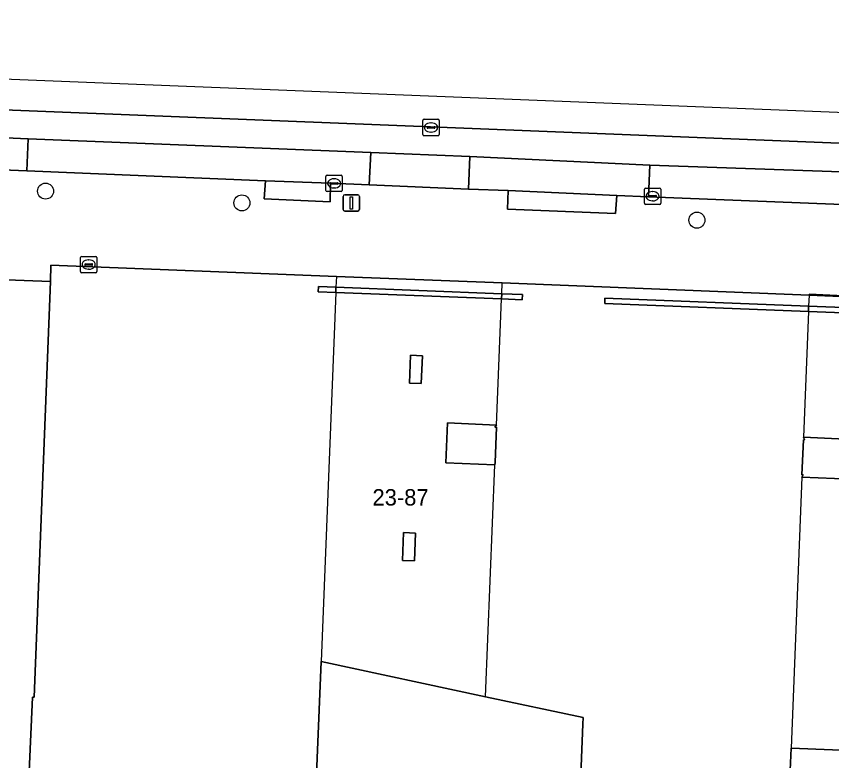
# Model space of a CAD drawing. Extents: x 160888 to 161385, y 386490 to 386908.
# Drawn here: x 161220.29 to 161269.97, y 386857.07 to 386902.41 of the extents above; entities that cross this region are included whole.
import ezdxf

# ---------------------------------------------------------------- set-up
doc = ezdxf.new("R2010")
doc.units = 0
for name, color, linetype in [('IMGEO_Boom', 7, 'Continuous'), ('IMGEO_Erf', 7, 'Continuous'), ('IMGEO_Hek', 7, 'Continuous'), ('IMGEO_Kolk', 7, 'Continuous'), ('IMGEO_Lichtmast', 7, 'Continuous'), ('IMGEO_Muur', 7, 'Continuous'), ('IMGEO_Pand', 7, 'Continuous'), ('IMGEO_Pand_nummerreeks', 7, 'Continuous'), ('IMGEO_Pand_overbouw', 7, 'Continuous'), ('IMGEO_Parkeervlak_gesloten', 7, 'Continuous'), ('IMGEO_Rijbaan_lokaal_gesloten', 7, 'Continuous'), ('IMGEO_Rioolput', 7, 'Continuous'), ('IMGEO_Voetpad_open', 7, 'Continuous')]:
    doc.layers.add(name, color=color, linetype=linetype)

msp = doc.modelspace()

# ---------------------------------------------------------------- linework, layer by layer
at = {"layer": 'IMGEO_Boom'}
for centre in [(161222.068, 386891.761), (161234.033, 386891.042), (161261.759, 386889.993)]:
    msp.add_circle(centre, 0.489, dxfattribs=at)
at = {"layer": 'IMGEO_Erf'}
msp.add_lwpolyline([(161278.689, 386885.003), (161268.594, 386885.414), (161249.896, 386886.171), (161239.793, 386886.567), (161222.396, 386887.248), (161222.369, 386886.248), (161221.375, 386860.939), (161221.275, 386860.943), (161221.078, 386856.403), (161221.066, 386856.099), (161221.271, 386856.091), (161221.965, 386856.062), (161221.919, 386854.943), (161229.279, 386854.644), (161238.505, 386854.269), (161238.86, 386863.105), (161248.886, 386860.967), (161254.82, 386859.706), (161254.804, 386859.3), (161254.641, 386855.168), (161257.979, 386855.044), (161267.366, 386854.695), (161267.493, 386857.839), (161277.574, 386857.417)], dxfattribs=at)
for points in [[(161249.857, 386885.197), (161239.754, 386885.591), (161238.684, 386885.633), (161238.696, 386885.947), (161239.766, 386885.905), (161249.87, 386885.511), (161251.132, 386885.462), (161251.119, 386885.148)], [(161256.153, 386885.234), (161268.567, 386884.752), (161278.663, 386884.36), (161279.736, 386884.318), (161279.724, 386883.998), (161278.65, 386884.04), (161268.554, 386884.432), (161256.14, 386884.914)], [(161244.242, 386880.066), (161244.315, 386881.769), (161245.032, 386881.738), (161244.959, 386880.036)], [(161249.458, 386875.226), (161249.452, 386875.087), (161246.455, 386875.203), (161246.559, 386877.641), (161249.549, 386877.514), (161249.453, 386877.378), (161249.544, 386877.375)], [(161268.243, 386876.619), (161268.307, 386876.617), (161268.249, 386876.768), (161271.239, 386876.642), (161271.137, 386874.214), (161268.151, 386874.333), (161268.226, 386874.47), (161268.157, 386874.473)], [(161244.542, 386869.236), (161243.815, 386869.264), (161243.879, 386870.962), (161244.606, 386870.935)]]:
    msp.add_lwpolyline(points, close=True, dxfattribs=at)
at = {"layer": 'IMGEO_Hek'}
for points in [[(161249.544, 386877.375), (161249.453, 386877.378), (161249.549, 386877.514)], [(161268.249, 386876.768), (161268.307, 386876.617), (161268.243, 386876.619)], [(161249.452, 386875.087), (161249.458, 386875.226)], [(161268.157, 386874.473), (161268.226, 386874.47), (161268.151, 386874.333)]]:
    msp.add_lwpolyline(points, dxfattribs=at)
at = {"layer": 'IMGEO_Kolk'}
for p, q in [((161239.15, 386891.807), (161239.15, 386892.659)), ((161239.225, 386892.733), (161240.077, 386892.733)), ((161239.638, 386892.513), (161239.663, 386892.513)), ((161240.151, 386892.659), (161240.151, 386891.807)), ((161239.409, 386892.227), (161239.409, 386892.239)), ((161239.847, 386892.19), (161239.449, 386892.19)), ((161239.452, 386892.276), (161239.85, 386892.276)), ((161239.893, 386892.239), (161239.893, 386892.227)), ((161240.077, 386891.733), (161239.225, 386891.733)), ((161239.661, 386891.953), (161239.636, 386891.953)), ((161258.557, 386891.024), (161258.557, 386891.876)), ((161258.632, 386891.95), (161259.484, 386891.95)), ((161258.859, 386891.493), (161259.257, 386891.493)), ((161259.045, 386891.73), (161259.07, 386891.73)), ((161259.558, 386891.876), (161259.558, 386891.024)), ((161258.816, 386891.444), (161258.816, 386891.456)), ((161259.254, 386891.407), (161258.856, 386891.407)), ((161259.068, 386891.17), (161259.043, 386891.17)), ((161259.3, 386891.456), (161259.3, 386891.444)), ((161259.484, 386890.95), (161258.632, 386890.95))]:
    msp.add_line(p, q, dxfattribs=at)
for points in [[(161239.15, 386891.807), (161239.15, 386892.659)], [(161239.225, 386892.733), (161240.077, 386892.733)], [(161240.151, 386892.659), (161240.151, 386891.807)], [(161240.077, 386891.733), (161239.225, 386891.733)], [(161258.557, 386891.024), (161258.557, 386891.876)], [(161258.632, 386891.95), (161259.484, 386891.95)], [(161259.558, 386891.876), (161259.558, 386891.024)], [(161259.484, 386890.95), (161258.632, 386890.95)]]:
    msp.add_lwpolyline(points, dxfattribs=at)
for centre, radius, start, end in [((161239.227, 386892.657), 0.0765, 91.552, 178.448), ((161239.227, 386892.657), 0.0765, 91.552, 178.448), ((161240.075, 386892.657), 0.0765, 1.552, 88.448), ((161240.075, 386892.657), 0.0765, 1.552, 88.448), ((161239.449, 386892.236), 0.0403, 85.8775, 175.7526), ((161239.446, 386892.226), 0.0366, 178.938, 274.7102), ((161239.85, 386892.233), 0.043, 264.8664, 352.4533), ((161239.854, 386892.238), 0.0386, 1.7309, 96.639), ((161239.227, 386891.809), 0.0765, 181.552, 268.448), ((161239.227, 386891.809), 0.0765, 181.552, 268.448), ((161240.075, 386891.809), 0.0765, 271.552, 358.448), ((161240.075, 386891.809), 0.0765, 271.552, 358.448), ((161258.634, 386891.874), 0.0765, 91.552, 178.448), ((161258.634, 386891.874), 0.0765, 91.552, 178.448), ((161258.856, 386891.453), 0.0403, 85.8775, 175.7526), ((161259.261, 386891.455), 0.0386, 1.7309, 96.639), ((161259.482, 386891.874), 0.0765, 1.552, 88.448), ((161259.482, 386891.874), 0.0765, 1.552, 88.448), ((161258.634, 386891.026), 0.0765, 181.552, 268.448), ((161258.634, 386891.026), 0.0765, 181.552, 268.448), ((161258.853, 386891.443), 0.0366, 178.938, 274.7102), ((161259.257, 386891.45), 0.043, 264.8664, 352.4533), ((161259.482, 386891.026), 0.0765, 271.552, 358.448), ((161259.482, 386891.026), 0.0765, 271.552, 358.448)]:
    msp.add_arc(centre, radius, start, end, dxfattribs=at)
for centre, major_axis, ratio, start_param, end_param in [((161239.637, 386892.233), (-0.387, 0.002), 0.722429, 4.712389, 7.853982), ((161239.662, 386892.233), (-0.39, 0.002), 0.717154, 1.570796, 4.712389), ((161259.044, 386891.45), (-0.387, 0.002), 0.722429, 4.712389, 7.853982), ((161259.069, 386891.45), (-0.39, 0.002), 0.717154, 1.570796, 4.712389)]:
    msp.add_ellipse(centre, major_axis=major_axis, ratio=ratio, start_param=start_param, end_param=end_param, dxfattribs=at)
at = {"layer": 'IMGEO_Lichtmast'}
for p, q in [((161240.302, 386891.542), (161241.092, 386891.542)), ((161241.092, 386891.542), (161240.302, 386891.542)), ((161240.202, 386890.642), (161240.202, 386891.442)), ((161240.202, 386891.442), (161240.202, 386890.642)), ((161241.192, 386891.442), (161241.192, 386890.642)), ((161241.192, 386890.642), (161241.192, 386891.442)), ((161241.092, 386890.542), (161240.302, 386890.542)), ((161240.302, 386890.542), (161241.092, 386890.542))]:
    msp.add_line(p, q, dxfattribs=at)
msp.add_lwpolyline([(161240.622, 386891.417), (161240.772, 386891.417), (161240.772, 386890.667), (161240.622, 386890.667), (161240.622, 386891.417)], dxfattribs=at)
for centre, start, end in [((161240.302, 386891.442), 90, 180), ((161240.302, 386891.442), 90, 180), ((161241.092, 386891.442), 0, 90), ((161241.092, 386891.442), 360, 90), ((161240.302, 386890.642), 180, 270), ((161240.302, 386890.642), 180, 270), ((161241.092, 386890.642), 270, 0), ((161241.092, 386890.642), 270, 0)]:
    msp.add_arc(centre, 0.1, start, end, dxfattribs=at)
at = {"layer": 'IMGEO_Muur'}
for points in [[(161238.696, 386885.947), (161238.684, 386885.633), (161239.754, 386885.591), (161239.766, 386885.905)], [(161239.766, 386885.905), (161239.754, 386885.591), (161249.857, 386885.197), (161249.87, 386885.511)], [(161251.119, 386885.148), (161251.132, 386885.462), (161249.87, 386885.511), (161249.857, 386885.197)], [(161256.153, 386885.234), (161256.14, 386884.914), (161268.554, 386884.432), (161268.567, 386884.752)], [(161268.567, 386884.752), (161268.554, 386884.432), (161278.65, 386884.04), (161278.663, 386884.36)]]:
    msp.add_lwpolyline(points, close=True, dxfattribs=at)
at = {"layer": 'IMGEO_Pand'}
for points in [[(161238.86, 386863.105), (161238.505, 386854.269), (161229.279, 386854.644), (161221.919, 386854.943), (161221.965, 386856.062), (161221.271, 386856.091), (161221.066, 386856.099), (161221.078, 386856.403), (161221.275, 386860.943), (161221.375, 386860.939), (161222.369, 386886.248), (161210.581, 386886.706), (161210.559, 386886.386), (161210.538, 386886.09)], [(161208.047, 386882.906), (161205.549, 386883.004), (161205.23, 386883.017), (161203.943, 386850.322), (161203.707, 386843.159), (161282.19, 386840.045), (161283.986, 386839.974), (161284.468, 386852.014), (161284.901, 386852.005), (161284.908, 386852.43), (161283.395, 386852.488), (161277.385, 386852.718), (161277.574, 386857.417), (161267.493, 386857.839), (161267.366, 386854.695), (161257.979, 386855.044), (161254.641, 386855.168), (161254.804, 386859.3), (161254.82, 386859.706), (161248.886, 386860.967), (161238.86, 386863.105)]]:
    msp.add_lwpolyline(points, dxfattribs=at)
for points in [[(161245.032, 386881.738), (161244.315, 386881.769), (161244.242, 386880.066), (161244.959, 386880.036)], [(161246.559, 386877.641), (161246.455, 386875.203), (161249.452, 386875.087), (161249.458, 386875.226), (161249.544, 386877.375), (161249.453, 386877.378), (161249.549, 386877.514)], [(161271.137, 386874.214), (161271.239, 386876.642), (161268.249, 386876.768), (161268.307, 386876.617), (161268.243, 386876.619), (161268.157, 386874.473), (161268.226, 386874.47), (161268.151, 386874.333)], [(161244.606, 386870.935), (161243.879, 386870.962), (161243.815, 386869.264), (161244.542, 386869.236)]]:
    msp.add_lwpolyline(points, close=True, dxfattribs=at)
at = {"layer": 'IMGEO_Pand_overbouw'}
for points in [[(161249.896, 386886.171), (161239.793, 386886.567), (161239.766, 386885.905), (161239.754, 386885.591), (161238.86, 386863.105), (161248.886, 386860.967), (161249.452, 386875.087), (161246.455, 386875.203), (161246.559, 386877.641), (161249.549, 386877.514), (161249.857, 386885.197), (161249.87, 386885.511)], [(161268.597, 386885.494), (161268.594, 386885.414), (161268.567, 386884.752), (161268.554, 386884.432), (161268.249, 386876.768), (161271.239, 386876.642), (161271.137, 386874.214), (161268.151, 386874.333), (161267.493, 386857.839), (161277.574, 386857.417), (161278.65, 386884.04), (161278.663, 386884.36), (161278.689, 386885.003)]]:
    msp.add_lwpolyline(points, close=True, dxfattribs=at)
at = {"layer": 'IMGEO_Parkeervlak_gesloten'}
for points in [[(161221.008, 386894.938), (161209.056, 386895.484), (161208.945, 386893.49), (161220.937, 386892.996)], [(161247.927, 386893.867), (161241.882, 386894.123), (161241.794, 386892.138), (161247.831, 386891.89)]]:
    msp.add_lwpolyline(points, close=True, dxfattribs=at)
msp.add_lwpolyline([(161277.593, 386892.717), (161276.971, 386892.717), (161258.887, 386893.342), (161258.81, 386891.423), (161274.2, 386890.804)], dxfattribs=at)
at = {"layer": 'IMGEO_Rijbaan_lokaal_gesloten'}
msp.add_lwpolyline([(161291.165, 386895.721), (161123.374, 386902.409), (161123.263, 386900.56), (161248.069, 386895.57), (161278.544, 386894.358), (161279.11, 386894.349), (161286.088, 386894.243)], dxfattribs=at)
for points in [[(161279.11, 386894.349), (161278.544, 386894.358), (161248.069, 386895.57), (161123.263, 386900.56), (161123.188, 386898.901), (161155.904, 386897.594), (161176.778, 386896.8), (161194.86, 386896.072), (161209.056, 386895.484), (161221.008, 386894.938), (161241.882, 386894.123), (161247.927, 386893.867), (161258.887, 386893.342), (161276.971, 386892.717), (161277.593, 386892.717), (161277.832, 386892.705), (161279.059, 386892.659)], [(161241.882, 386894.123), (161221.008, 386894.938), (161220.937, 386892.996), (161235.468, 386892.398), (161239.425, 386892.236), (161241.794, 386892.138)], [(161258.887, 386893.342), (161247.927, 386893.867), (161247.831, 386891.89), (161250.255, 386891.79), (161256.885, 386891.501), (161258.81, 386891.423)]]:
    msp.add_lwpolyline(points, close=True, dxfattribs=at)
at = {"layer": 'IMGEO_Rioolput'}
for p, q in [((161245.054, 386895.212), (161245.054, 386896.064)), ((161245.129, 386896.138), (161245.981, 386896.138)), ((161246.055, 386896.064), (161246.055, 386895.212)), ((161245.313, 386895.632), (161245.313, 386895.644)), ((161245.751, 386895.595), (161245.353, 386895.595)), ((161245.356, 386895.681), (161245.754, 386895.681)), ((161245.542, 386895.918), (161245.567, 386895.918)), ((161245.797, 386895.644), (161245.797, 386895.632)), ((161245.981, 386895.138), (161245.129, 386895.138)), ((161245.565, 386895.358), (161245.54, 386895.358)), ((161224.196, 386886.862), (161224.196, 386887.714)), ((161224.271, 386887.788), (161225.123, 386887.788)), ((161224.684, 386887.568), (161224.709, 386887.568)), ((161225.197, 386887.714), (161225.197, 386886.862)), ((161224.455, 386887.282), (161224.455, 386887.294)), ((161224.893, 386887.245), (161224.495, 386887.245)), ((161224.498, 386887.331), (161224.896, 386887.331)), ((161224.707, 386887.008), (161224.682, 386887.008)), ((161224.939, 386887.294), (161224.939, 386887.282)), ((161225.123, 386886.788), (161224.271, 386886.788))]:
    msp.add_line(p, q, dxfattribs=at)
for points in [[(161245.054, 386895.212), (161245.054, 386896.064)], [(161245.129, 386896.138), (161245.981, 386896.138)], [(161246.055, 386896.064), (161246.055, 386895.212)], [(161245.981, 386895.138), (161245.129, 386895.138)], [(161224.196, 386886.862), (161224.196, 386887.714)], [(161224.271, 386887.788), (161225.123, 386887.788)], [(161225.197, 386887.714), (161225.197, 386886.862)], [(161225.123, 386886.788), (161224.271, 386886.788)]]:
    msp.add_lwpolyline(points, dxfattribs=at)
for centre, radius, start, end in [((161245.131, 386896.062), 0.0765, 91.552, 178.448), ((161245.131, 386896.062), 0.0765, 91.552, 178.448), ((161245.979, 386896.062), 0.0765, 1.552, 88.448), ((161245.979, 386896.062), 0.0765, 1.552, 88.448), ((161245.353, 386895.641), 0.0403, 85.8775, 175.7526), ((161245.35, 386895.631), 0.0366, 178.938, 274.7102), ((161245.754, 386895.638), 0.043, 264.8664, 352.4533), ((161245.758, 386895.643), 0.0386, 1.7309, 96.639), ((161245.131, 386895.214), 0.0765, 181.552, 268.448), ((161245.131, 386895.214), 0.0765, 181.552, 268.448), ((161245.979, 386895.214), 0.0765, 271.552, 358.448), ((161245.979, 386895.214), 0.0765, 271.552, 358.448), ((161224.273, 386887.712), 0.0765, 91.552, 178.448), ((161224.273, 386887.712), 0.0765, 91.552, 178.448), ((161225.121, 386887.712), 0.0765, 1.552, 88.448), ((161225.121, 386887.712), 0.0765, 1.552, 88.448), ((161224.495, 386887.291), 0.0403, 85.8775, 175.7526), ((161224.492, 386887.281), 0.0366, 178.938, 274.7102), ((161224.896, 386887.288), 0.043, 264.8664, 352.4533), ((161224.9, 386887.293), 0.0386, 1.7309, 96.639), ((161224.273, 386886.864), 0.0765, 181.552, 268.448), ((161224.273, 386886.864), 0.0765, 181.552, 268.448), ((161225.121, 386886.864), 0.0765, 271.552, 358.448), ((161225.121, 386886.864), 0.0765, 271.552, 358.448)]:
    msp.add_arc(centre, radius, start, end, dxfattribs=at)
for centre, major_axis, ratio, start_param, end_param in [((161245.541, 386895.638), (-0.387, 0.002), 0.722429, 4.712389, 7.853982), ((161245.566, 386895.638), (-0.39, 0.002), 0.717154, 1.570796, 4.712389), ((161224.683, 386887.288), (-0.387, 0.002), 0.722429, 4.712389, 7.853982), ((161224.708, 386887.288), (-0.39, 0.002), 0.717154, 1.570796, 4.712389)]:
    msp.add_ellipse(centre, major_axis=major_axis, ratio=ratio, start_param=start_param, end_param=end_param, dxfattribs=at)
at = {"layer": 'IMGEO_Voetpad_open'}
for points in [[(161274.2, 386890.804), (161258.81, 386891.423), (161256.885, 386891.501), (161256.805, 386890.402), (161250.217, 386890.662), (161250.255, 386891.79), (161247.831, 386891.89), (161241.794, 386892.138), (161239.425, 386892.236), (161239.41, 386891.107), (161235.397, 386891.29), (161235.468, 386892.398), (161220.937, 386892.996), (161208.945, 386893.49), (161207.063, 386893.567), (161206.996, 386892.136), (161196.74, 386892.515), (161196.781, 386894.009), (161194.801, 386894.087), (161176.703, 386894.8), (161176.66, 386894.802), (161176.601, 386893.617), (161155.57, 386894.474), (161155.616, 386895.637)], [(161127.058, 386890.969), (161178.427, 386888.94), (161188.186, 386888.554), (161196.395, 386888.23), (161196.381, 386887.886), (161205.414, 386887.602), (161205.385, 386886.913), (161206.029, 386886.888), (161210.581, 386886.706), (161222.369, 386886.248), (161222.396, 386887.248), (161239.793, 386886.567), (161249.896, 386886.171), (161268.594, 386885.414), (161278.689, 386885.003), (161279.034, 386891.63), (161279.059, 386892.659), (161277.832, 386892.705), (161277.593, 386892.717)]]:
    msp.add_lwpolyline(points, dxfattribs=at)
for points in [[(161239.425, 386892.236), (161235.468, 386892.398), (161235.397, 386891.29), (161239.41, 386891.107)], [(161256.885, 386891.501), (161250.255, 386891.79), (161250.217, 386890.662), (161256.805, 386890.402)]]:
    msp.add_lwpolyline(points, close=True, dxfattribs=at)

# ---------------------------------------------------------------- texts
at = {"layer": 'IMGEO_Pand_nummerreeks'}
msp.add_text('23-87', height=1, dxfattribs=at).set_placement((161241.989, 386872.609))

doc.saveas('drawing.dxf')
